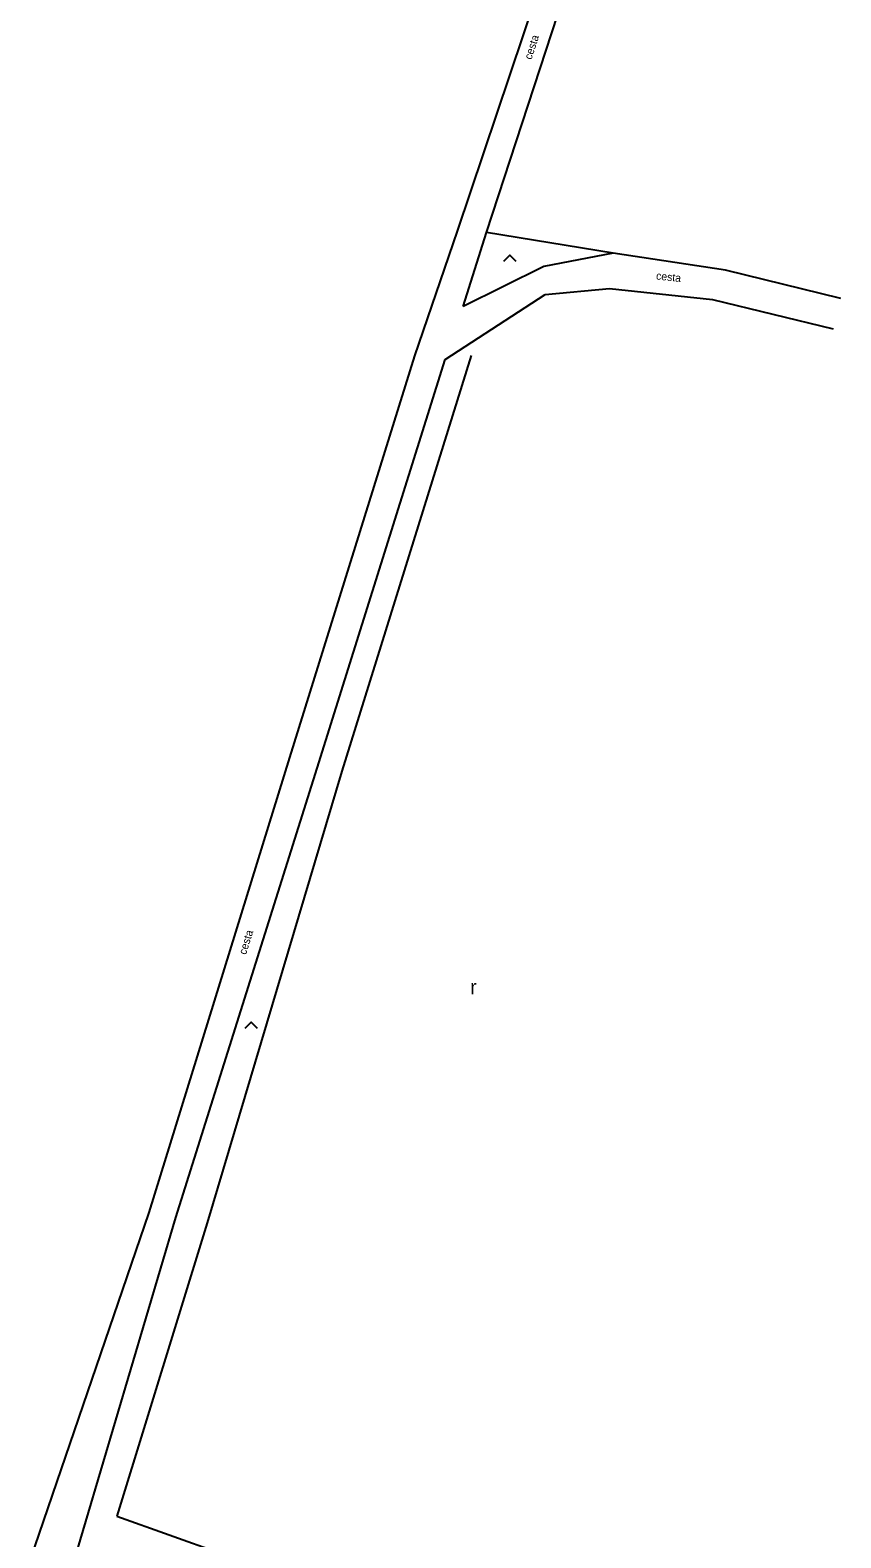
# Model space of a CAD drawing. Extents: x -539244 to -537359, y -1183785 to -1181851.
# Drawn here: x -538513.3 to -538445.9, y -1183233.2 to -1183108 of the extents above; entities that cross this region are included whole.
import ezdxf

# ---------------------------------------------------------------- set-up
doc = ezdxf.new("R2010")
doc.units = 0
for name, color, linetype in [('Vrstva 11', 7, 'Continuous'), ('Vrstva 21', 7, 'Continuous'), ('Vrstva 36', 7, 'Continuous'), ('Vrstva 40', 7, 'Continuous')]:
    doc.layers.add(name, color=color, linetype=linetype)

msp = doc.modelspace()

# ---------------------------------------------------------------- linework, layer by layer
at = {"layer": 'Vrstva 11'}
for p, q in [((-538468.32, -1183096.51), (-538477.79, -1183124.73)), ((-538475.35, -1183124.85), (-538466.24, -1183096.95)), ((-538477.79, -1183124.73), (-538481.34, -1183135.08)), ((-538477.28, -1183130.99), (-538475.35, -1183124.85)), ((-538464.83, -1183126.57), (-538470.58, -1183127.67)), ((-538455.49, -1183127.98), (-538464.83, -1183126.57)), ((-538470.58, -1183127.67), (-538477.28, -1183130.99)), ((-538445.92, -1183130.32), (-538455.49, -1183127.98)), ((-538470.47, -1183130), (-538465.13, -1183129.5)), ((-538465.13, -1183129.5), (-538456.57, -1183130.4)), ((-538478.8, -1183135.39), (-538470.47, -1183130)), ((-538456.57, -1183130.4), (-538446.57, -1183132.83)), ((-538481.34, -1183135.08), (-538491.73, -1183168.43)), ((-538489.42, -1183169.29), (-538478.8, -1183135.39)), ((-538491.73, -1183168.43), (-538503.4, -1183206.19)), ((-538501.15, -1183206.59), (-538489.42, -1183169.29)), ((-538503.4, -1183206.19), (-538513.26, -1183234.98)), ((-538510.03, -1183236.52), (-538501.15, -1183206.59))]:
    msp.add_line(p, q, dxfattribs=at)
at = {"layer": 'Vrstva 21'}
for p, q in [((-538464.83, -1183126.57), (-538475.35, -1183124.85)), ((-538476.63, -1183135.04), (-538487.36, -1183169.56)), ((-538487.36, -1183169.56), (-538498.55, -1183207.05)), ((-538498.55, -1183207.05), (-538506.06, -1183231.39)), ((-538506.06, -1183231.39), (-538487.28, -1183238.06))]:
    msp.add_line(p, q, dxfattribs=at)
at = {"layer": 'Vrstva 36'}
for points in [[(-538473.911, -1183127.234), (-538473.411, -1183126.734), (-538472.911, -1183127.234)], [(-538495.394, -1183190.88), (-538494.894, -1183190.38), (-538494.394, -1183190.88)]]:
    msp.add_lwpolyline(points, dxfattribs=at)

# ---------------------------------------------------------------- texts
msp.add_text('r', height=1.2, dxfattribs=at).set_placement((-538476.707, -1183188.061))
at = {"layer": 'Vrstva 40'}
for rotation, p in [(71.91693, (-538471.624, -1183110.542)), (353.99796, (-538461.293, -1183128.74)), (72.54283, (-538495.338, -1183184.83))]:
    msp.add_text('cesta', height=0.65, rotation=rotation, dxfattribs=at).set_placement(p)

doc.saveas('drawing.dxf')
